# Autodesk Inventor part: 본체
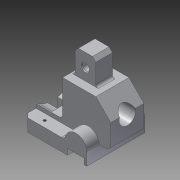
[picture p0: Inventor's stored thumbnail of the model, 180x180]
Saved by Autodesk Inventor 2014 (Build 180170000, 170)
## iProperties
Created: 2016-11
Part Number: 본체
Material: 알루미늄 6061
Document SubType Name: Modeling
Designer: USER
Density: 2.71 g/cm^3
Appearance: 알루미늄 - 평지
Mass: 477.197 g
Surface Area: 324.806 cm^2
Volume: 176.087 cm^3
Author: USER
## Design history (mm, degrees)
sketch "스케치1"
  geometry: L1 (0, 0)-(0, -30); L2 (0, 0)-(18, 18); L3 (18, 18)-(58, 18); L4 (58, 18)-(58, -25); L5 (58, -25)-(90, -25); L6 (90, -25)-(90, -30); L7 (90, -30)-(0, -30)
  constraints: 14 end point, 5 perpendicular, 1 vertical
  dimensions: "d0" = 30 distance of L1.start L1.end; "d1" = 48 vertical distance of L1.end L2.end; "d2" = 45 deg angle of L3 L2; "d3" = 90 distance of L6.end L1.end; "d4" = 58 horizontal distance of L3.end L1.start; "d5" = 5 distance between parallel lines of L7 L5
extrude "돌출1" new body sketch "스케치1" stored distance "d6" = 40; taper "d7" = 0 deg
sketch "스케치3"
  geometry: L1 (58, 18)-(18, 18) reference; L2 (28, 18)-(53, 18); L3 (53, 18)-(53, 48); L4 (53, 48)-(28, 48); L5 (28, 48)-(28, 18); L6 (58, 18)-(58, -25) reference; 1 further point
  constraints: 8 end point, 2 parallel, 1 horizontal, 1 perpendicular, 1 point on line
  dimensions: "d9" = 25 distance of L3.end L4.end; "d10" = 5 distance between parallel lines of L6 L3; "d11" = 30 distance between parallel lines of L1 L4
extrude "돌출2" join sketch "스케치3" stored distance "d12" = 20; taper "d13" = 0 deg
chamfer "모따기1" distance "d14" = 4; stored, may be unused: second distance "d15" = 2, angle "d16" = 45 deg
sketch "스케치5"
  geometry: L1 (58, -25)-(90, -25) reference; L2 (90, -45)-(37, -45); L3 (90, -30)-(40, -30); L4 (14, -30)-(14, -45); L5 (14, -45)-(17, -45); L6 (37, -45)-(37, -38); L7 (37, -38)-(17, -38); L8 (17, -38)-(17, -45); L9 (90, -45)-(90, -30); A1 r 13 centre (27, -30) between (40, -30) and (14, -30); 1 further point
  constraints: 16 end point, 3 perpendicular, 2 horizontal alignment, 2 parallel, 2 point on circle, 1 centre point, 1 tangent, 1 vertical alignment
  dimensions: "d17" = 20 distance of L1.end L2.start; "d18" = 26 diameter of A1; "d20" = 15 distance from line of L2 A1.centre; "d21" = 15 distance between parallel lines of L2 L3; "d22" = 15 distance of L4.start L4.end; "d23" = 3 distance of L4.end L5.end; "d26" = 7 distance of L2.end L6.end; "d27" = 20 distance of L6.end L7.end; "d28" = 76 distance from line of L4.start L9
extrude "돌출3" join sketch "스케치5" stored distance "d29" = 70; taper "d30" = 0 deg
sketch "스케치7"
  geometry: L1 (-63, -15)-(-63, 55) reference; C1 r 14.5 at (-21, 20); 1 further point
  constraints: 1 centre point, 1 horizontal alignment
  dimensions: "d31" = 29 diameter of C1; "d32" = 42 distance from line of L1 C1.centre
extrude "돌출4" cut sketch "스케치7" distance "d33" = 7; taper "d34" = 0 deg
sketch "스케치8"
  geometry: C1 r 14.5 at (0, 0) reference; C2 r 10 at (0, 0); 1 further point
  constraints: 1 centre point, 1 coincident
  dimensions: "d35" = 20 diameter of C2
extrude "돌출5" cut sketch "스케치8" distance "d36" = 124.5; taper "d37" = 0 deg
chamfer "모따기2" distance "d38" = 1; stored, may be unused: second distance "d39" = 2, angle "d40" = 45 deg
node "작업 평면1"
sketch "스케치9"
  geometry: L1 (-20, 55)-(-20, -15) reference; L2 (-6.373, 26)-(-20, 26); L3 (-20, 26)-(-20, 14); L4 (-20, 14)-(-6.373, 14); L5 (0, 0)-(0, 40) reference; L6 (0, 38.894)-(0, 1.106); C1 r 14.5 at (22, 20) reference; A1 r 29 centre (22, 20) between (0, 38.894) and (-6.373, 26); A2 r 29 centre (22, 20) between (-6.373, 14) and (0, 1.106); 2 further points
  constraints: 8 end point, 4 point on circle, 4 point on line, 2 centre point, 2 perpendicular, 1 coincident, 1 collinear, 1 horizontal alignment, 1 midpoint
  dimensions: "d43" = 12 distance of L3.end L2.end; "d44" = 29 radius of A1; "d45" = 29 radius of A2
extrude "돌출6" cut sketch "스케치9" distance "d46" = 97; taper "d47" = 0 deg
sketch "스케치10"
  geometry: L1 (0, 15)-(0, 0) reference; L2 (18, 7.5)-(18, -47.5); 2 further points
  constraints: 2 end point, 1 horizontal alignment, 1 midpoint, 1 parallel, 1 vertical alignment
  dimensions: "d48" = 18 distance from line of L2.start L1; "d49" = 55 distance of L2.end L2.start
hole "구멍1" sketch "스케치10" at (18, 7.5), (18, -47.5) diameter "d50" = 3.242; stored, may be unused: countersink angle "d54" = 90 deg, drill point angle "d56" = 118 deg; dims "d51" = 20, "d52" = 4, "d53" = 2, "d55" = 8
sketch "스케치11"
  geometry: L1 (-28, -44)-(-28, -18) reference; L2 (-37, 45)-(-90, 45) reference; C1 r 4 at (-40.5, -32); 1 further point
  constraints: 1 centre point
  dimensions: "d57" = 8 diameter of C1; "d58" = 12.5 distance from line of L1 C1.centre; "d59" = 77 distance from line of L2 C1.centre
extrude "돌출7" cut sketch "스케치11" distance "d60" = 97; taper "d61" = 0 deg
chamfer "모따기3" distance "d62" = 1; stored, may be unused: second distance "d63" = 2, angle "d64" = 45 deg
fillet "모깎기1" dims "d65" = 3
fillet "모깎기2" dims "d66" = 5
fillet "모깎기3" dims "d67" = 3
sketch "스케치12"
  geometry: L1 (-58, 22)-(-58, -18) reference; L2 (-58, -18)-(-18, -18) reference; 1 further point
  constraints: 1 other
  dimensions: "d68" = 18 distance from line of L2 point (-33, 0); "d69" = 25 distance from line of L1 point (-33, 0)
feature "엠보싱1" sketch "스케치12" dims "d0" = 30, "d1" = 48, "d2" = 45 deg, "d3" = 90, "d4" = 58, "d5" = 5, "d70" = 0.5, "d71" = 0
chamfer "모따기4" distance "d72" = 5; stored, may be unused: second distance "d73" = 2, angle "d74" = 45 deg
node "솔리드1"
other parameters: "d41" = -18, "d42" = 58
